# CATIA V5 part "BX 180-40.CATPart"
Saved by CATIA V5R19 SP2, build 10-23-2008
Part number: BX 180-40
Bounding box of the stored display mesh (mm): x -24.865 to 24.865, y -24.997 to 24.997, z 0 to 190
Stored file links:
  C:\Users\Bora\Desktop\3D Katı model\BX serisi\BX 180\BX 180-40.CATPart
  C:\Program Files\Dassault Systemes\B19\intel_a\reffiles\standard\MetricThickPitch.txt
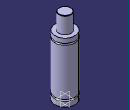
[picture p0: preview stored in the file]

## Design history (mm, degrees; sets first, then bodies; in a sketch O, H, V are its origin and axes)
Body1 (main body)
  Sketch1 on yz-plane, origin (0, 0, 0), H (0, 1, 0), V (0, 0, 1)
    point P1 (25, 12.5)
    point P2 (25, 16.5)
    arc A1 centre (25, 14.5) radius 2 from (25, 16.5) to (25, 12.5) ccw
    point P3 (25, 133.5)
    point P4 (25, 137.5)
    arc A2 centre (25, 135.5) radius 2 from (25, 137.5) to (25, 133.5) ccw
    point P5 (25, 137.5)
    line L1 (25, 149) -> (25, 137.5)
    point P8 (15, 189)
    line L2 (15, 189) -> (15, 149)
    point P10 (15, 189)
    arc A3 centre (14, 189) radius 1 from (15, 189) to (14, 190) ccw
    point P11 (25, 16.5)
    point P12 (25, 133.5)
    line L3 (25, 133.5) -> (25, 16.5)
    point P14 (25, 12.5)
    line L4 (25, 12.5) -> (25, 0)
    line L5 (14, 190) -> (0, 190)
    line L6 (15, 149) -> (25, 149)
    line L7 (25, 0) -> (0, 0)
    tangency: L5 A3
    horizontal: L6 H, L7 H
    coincidence: P1 P14, P2 P11, P3 P12, P4 P5, P8 P10
  Shaft1: profile Sketch1, axis Sketch1.V, angle 360
  Sketch2 on face of Shaft1 from Sketch1.L7, origin (0, 0, 0), H (1, 0, 0), V (0, -1, 0)
    point P1 (12.5, 0)
    distance P1 V = 12.5
  Hole1: placed by Sketch2, at (12.5, 0, 0) direction (0, 0, 1), diameter 4.917, depth 6, threaded "M6", thread diameter 6, thread depth 6, pitch 1
  Sketch3 on face of Shaft1 from Sketch1.L7, origin (0, 0, 0), H (1, 0, 0), V (0, -1, 0)
    point P1 (-12.5, 0)
    distance P1 V = 12.5
  Hole2: placed by Sketch3, at (-12.5, 0, 0) direction (0, 0, 1), diameter 4.917, depth 6, threaded "M6", thread diameter 6, thread depth 6, pitch 1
